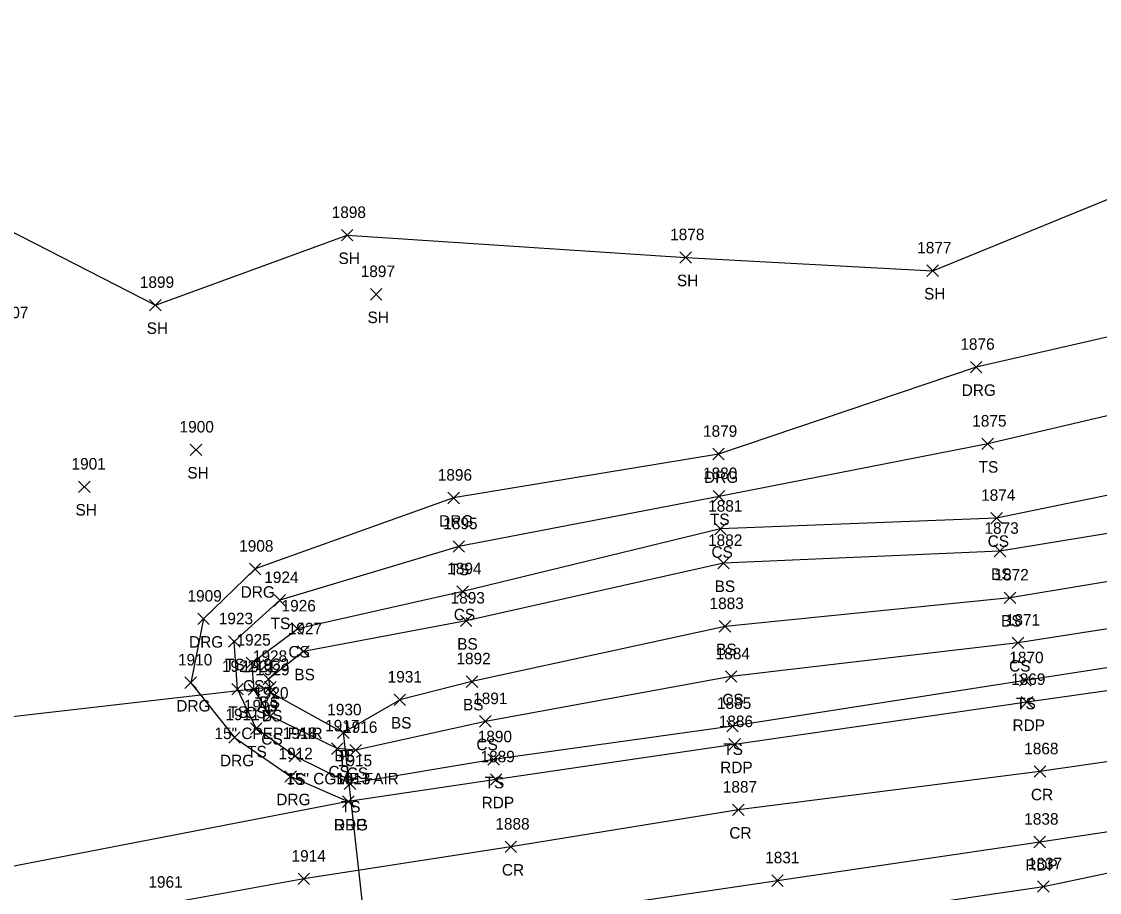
# Model space of a CAD drawing. Extents: x 1472233 to 1475777, y 540726 to 543442.
# Drawn here: x 1475192.5 to 1475379.6, y 543285.3 to 543436.6 of the extents above; entities that cross this region are included whole.
import ezdxf

# ---------------------------------------------------------------- set-up
doc = ezdxf.new("R2010")
doc.units = 0
for name, color, linetype in [('D_A', 7, 'Continuous'), ('D_C', 7, 'Continuous'), ('D_I', 7, 'Continuous'), ('D_TIC', 7, 'Continuous'), ('DCP', 7, 'Continuous'), ('L_A', 7, 'Continuous'), ('L_I', 7, 'Continuous'), ('L_TIC', 7, 'Continuous'), ('LELB', 7, 'Continuous'), ('LSOGP', 7, 'Continuous'), ('P_A', 7, 'Continuous'), ('P_I', 7, 'Continuous'), ('P_TIC', 7, 'Continuous'), ('PET', 7, 'Continuous'), ('PRC', 7, 'Continuous'), ('R_A', 7, 'Continuous'), ('R_I', 7, 'Continuous'), ('R_TIC', 7, 'Continuous'), ('RDG', 7, 'Continuous')]:
    doc.layers.add(name, color=color, linetype=linetype)

msp = doc.modelspace()

# ---------------------------------------------------------------- linework, layer by layer
at = {"layer": 'D_TIC'}
for points in [[(1475234.68, 543319.97), (1475236.68, 543321.97)], [(1475236.68, 543319.97), (1475234.68, 543321.97)], [(1475247.33, 543312.1), (1475249.33, 543314.1)], [(1475249.33, 543312.1), (1475247.33, 543314.1)]]:
    msp.add_lwpolyline(points, dxfattribs=at)
at = {"layer": 'DCP'}
for points in [[(1475235.68, 543320.97), (1475182.74, 543314.89)], [(1475248.33, 543313.1), (1475253.84, 543263.18)]]:
    msp.add_lwpolyline(points, dxfattribs=at)
at = {"layer": 'L_TIC'}
for points in [[(1475248.02, 543398.5), (1475250.02, 543400.5)], [(1475250.02, 543398.5), (1475248.02, 543400.5)], [(1475306.77, 543394.64), (1475308.77, 543396.64)], [(1475308.77, 543394.64), (1475306.77, 543396.64)], [(1475349.65, 543392.34), (1475351.65, 543394.34)], [(1475351.65, 543392.34), (1475349.65, 543394.34)], [(1475253.05, 543388.23), (1475255.05, 543390.23)], [(1475255.05, 543388.23), (1475253.05, 543390.23)], [(1475214.72, 543386.35), (1475216.72, 543388.35)], [(1475216.72, 543386.35), (1475214.72, 543388.35)], [(1475221.78, 543361.23), (1475223.78, 543363.23)], [(1475223.78, 543361.23), (1475221.78, 543363.23)], [(1475359.2, 543362.25), (1475361.2, 543364.25)], [(1475361.2, 543362.25), (1475359.2, 543364.25)], [(1475202.37, 543354.8), (1475204.37, 543356.8)], [(1475204.37, 543354.8), (1475202.37, 543356.8)], [(1475312.56, 543353.14), (1475314.56, 543355.14)], [(1475314.56, 543353.14), (1475312.56, 543355.14)], [(1475360.74, 543349.36), (1475362.74, 543351.36)], [(1475362.74, 543349.36), (1475360.74, 543351.36)], [(1475312.8, 543347.47), (1475314.8, 543349.47)], [(1475314.8, 543347.47), (1475312.8, 543349.47)], [(1475267.38, 543344.43), (1475269.38, 543346.43)], [(1475269.38, 543344.43), (1475267.38, 543346.43)], [(1475361.32, 543343.63), (1475363.32, 543345.63)], [(1475363.32, 543343.63), (1475361.32, 543345.63)], [(1475313.34, 543341.52), (1475315.34, 543343.52)], [(1475315.34, 543341.52), (1475313.34, 543343.52)], [(1475236.31, 543335.08), (1475238.31, 543337.08)], [(1475238.31, 543335.08), (1475236.31, 543337.08)], [(1475236.31, 543335.08), (1475238.31, 543337.08)], [(1475238.31, 543335.08), (1475236.31, 543337.08)], [(1475268.07, 543336.6), (1475270.07, 543338.6)], [(1475270.07, 543336.6), (1475268.07, 543338.6)], [(1475363.07, 543335.52), (1475365.07, 543337.52)], [(1475365.07, 543335.52), (1475363.07, 543337.52)], [(1475268.66, 543331.51), (1475270.66, 543333.51)], [(1475270.66, 543331.51), (1475268.66, 543333.51)], [(1475239.36, 543330.14), (1475241.36, 543332.14)], [(1475241.36, 543330.14), (1475239.36, 543332.14)], [(1475239.36, 543330.14), (1475241.36, 543332.14)], [(1475241.36, 543330.14), (1475239.36, 543332.14)], [(1475313.6, 543330.55), (1475315.6, 543332.55)], [(1475315.6, 543330.55), (1475313.6, 543332.55)], [(1475228.41, 543327.92), (1475230.41, 543329.92)], [(1475230.41, 543327.92), (1475228.41, 543329.92)], [(1475364.47, 543327.7), (1475366.47, 543329.7)], [(1475366.47, 543327.7), (1475364.47, 543329.7)], [(1475240.4, 543326.18), (1475242.4, 543328.18)], [(1475242.4, 543326.18), (1475240.4, 543328.18)], [(1475231.48, 543324.21), (1475233.48, 543326.21)], [(1475233.48, 543324.21), (1475231.48, 543326.21)], [(1475234.34, 543321.38), (1475236.34, 543323.38)], [(1475236.34, 543321.38), (1475234.34, 543323.38)], [(1475269.67, 543320.96), (1475271.67, 543322.96)], [(1475271.67, 543320.96), (1475269.67, 543322.96)], [(1475314.67, 543321.83), (1475316.67, 543323.83)], [(1475316.67, 543321.83), (1475314.67, 543323.83)], [(1475365.72, 543321.15), (1475367.72, 543323.15)], [(1475367.72, 543321.15), (1475365.72, 543323.15)], [(1475228.97, 543319.65), (1475230.97, 543321.65)], [(1475230.97, 543319.65), (1475228.97, 543321.65)], [(1475231.85, 543319.59), (1475233.85, 543321.59)], [(1475233.85, 543319.59), (1475231.85, 543321.59)], [(1475234.76, 543319.05), (1475236.76, 543321.05)], [(1475236.76, 543319.05), (1475234.76, 543321.05)], [(1475257.16, 543317.8), (1475259.16, 543319.8)], [(1475259.16, 543317.8), (1475257.16, 543319.8)], [(1475257.16, 543317.8), (1475259.16, 543319.8)], [(1475259.16, 543317.8), (1475257.16, 543319.8)], [(1475234.66, 543315), (1475236.66, 543317)], [(1475236.66, 543315), (1475234.66, 543317)], [(1475232.22, 543312.79), (1475234.22, 543314.79)], [(1475234.22, 543312.79), (1475232.22, 543314.79)], [(1475272, 543314.04), (1475274, 543316.04)], [(1475274, 543314.04), (1475272, 543316.04)], [(1475314.89, 543313.22), (1475316.89, 543315.22)], [(1475316.89, 543313.22), (1475314.89, 543315.22)], [(1475247.33, 543312.1), (1475249.33, 543314.1)], [(1475249.33, 543312.1), (1475247.33, 543314.1)], [(1475246.3, 543309.31), (1475248.3, 543311.31)], [(1475248.3, 543309.31), (1475246.3, 543311.31)], [(1475249.49, 543309.05), (1475251.49, 543311.05)], [(1475251.49, 543309.05), (1475249.49, 543311.05)], [(1475238.94, 543308), (1475240.94, 543310)], [(1475240.94, 543308), (1475238.94, 543310)], [(1475273.45, 543307.42), (1475275.45, 543309.42)], [(1475275.45, 543307.42), (1475273.45, 543309.42)], [(1475248.51, 543303.24), (1475250.51, 543305.24)], [(1475250.51, 543303.24), (1475248.51, 543305.24)], [(1475368.86, 543285.35), (1475370.86, 543287.35)], [(1475370.86, 543285.35), (1475368.86, 543287.35)]]:
    msp.add_lwpolyline(points, dxfattribs=at)
at = {"layer": 'LELB'}
for points in [[(1475453.86, 543383.84), (1475412.78, 543375.62), (1475360.2, 543363.25), (1475313.56, 543354.14), (1475268.38, 543345.43), (1475237.31, 543336.08)], [(1475458.45, 543363.65), (1475414.07, 543361.09), (1475361.74, 543350.36), (1475313.8, 543348.47), (1475269.07, 543337.6), (1475240.36, 543331.14)], [(1475459.28, 543356.57), (1475414.21, 543353.1), (1475362.32, 543344.63), (1475314.34, 543342.52), (1475269.66, 543332.51), (1475241.4, 543327.18), (1475235.34, 543322.38), (1475235.76, 543320.05), (1475248.33, 543313.1), (1475258.16, 543318.8)], [(1475459.86, 543350.78), (1475417.09, 543345.32), (1475364.07, 543336.52), (1475314.6, 543331.55), (1475270.67, 543321.96), (1475258.16, 543318.8)], [(1475460.84, 543342.99), (1475416.96, 543336.74), (1475365.47, 543328.7), (1475315.67, 543322.83), (1475273, 543315.04), (1475250.49, 543310.05), (1475247.3, 543310.31), (1475235.66, 543316), (1475232.85, 543320.59), (1475232.48, 543325.21), (1475240.36, 543331.14)], [(1475461.98, 543336.03), (1475417.45, 543330.03), (1475366.72, 543322.15), (1475315.89, 543314.22), (1475274.45, 543308.42), (1475249.51, 543304.24), (1475239.94, 543309), (1475233.22, 543313.79), (1475229.97, 543320.65), (1475229.41, 543328.92), (1475237.31, 543336.08)], [(1475154.58, 543252.15), (1475203.22, 543262.61), (1475246.6, 543268.28), (1475255.93, 543270.01), (1475266.88, 543271.35), (1475278.04, 543272.27), (1475324.55, 543279.73), (1475369.86, 543286.35), (1475414.45, 543295.77), (1475466.95, 543301.49)]]:
    msp.add_lwpolyline(points, dxfattribs=at)
at = {"layer": 'LSOGP'}
msp.add_lwpolyline([(1475175.93, 543407.71), (1475215.72, 543387.35), (1475249.02, 543399.5), (1475307.77, 543395.64), (1475350.65, 543393.34), (1475414.2, 543419.32)], dxfattribs=at)
at = {"layer": 'P_TIC'}
for points in [[(1475366.01, 543317.38), (1475368.01, 543319.38)], [(1475368.01, 543317.38), (1475366.01, 543319.38)], [(1475315.26, 543310.05), (1475317.26, 543312.05)], [(1475317.26, 543310.05), (1475315.26, 543312.05)], [(1475368.27, 543305.33), (1475370.27, 543307.33)], [(1475370.27, 543305.33), (1475368.27, 543307.33)], [(1475273.86, 543303.94), (1475275.86, 543305.94)], [(1475275.86, 543303.94), (1475273.86, 543305.94)], [(1475248.21, 543300.1), (1475250.21, 543302.1)], [(1475250.21, 543300.1), (1475248.21, 543302.1)], [(1475315.91, 543298.68), (1475317.91, 543300.68)], [(1475317.91, 543298.68), (1475315.91, 543300.68)], [(1475276.43, 543292.25), (1475278.43, 543294.25)], [(1475278.43, 543292.25), (1475276.43, 543294.25)], [(1475368.23, 543293.1), (1475370.23, 543295.1)], [(1475370.23, 543293.1), (1475368.23, 543295.1)], [(1475240.48, 543286.69), (1475242.48, 543288.69)], [(1475242.48, 543286.69), (1475240.48, 543288.69)], [(1475322.7, 543286.39), (1475324.7, 543288.39)], [(1475324.7, 543286.39), (1475322.7, 543288.39)]]:
    msp.add_lwpolyline(points, dxfattribs=at)
at = {"layer": 'PET'}
for points in [[(1475462.95, 543331.81), (1475417.84, 543325.59), (1475367.01, 543318.38), (1475316.26, 543311.05), (1475274.86, 543304.94), (1475249.21, 543301.1), (1475175.88, 543286.93), (1475120.06, 543270.79), (1475090.24, 543260.11)], [(1475087.91, 543220.85), (1475087.19, 543228.55), (1475096.96, 543238.31), (1475120.81, 543245.65), (1475153.05, 543255.59), (1475202.33, 543267.68), (1475249.58, 543276.45), (1475275.49, 543280.28), (1475323.7, 543287.39), (1475369.23, 543294.1), (1475413.44, 543300.77), (1475466.08, 543307.86)]]:
    msp.add_lwpolyline(points, dxfattribs=at)
at = {"layer": 'PRC'}
msp.add_lwpolyline([(1475464.44, 543319.89), (1475419.21, 543313.59), (1475369.27, 543306.33), (1475316.91, 543299.68), (1475277.43, 543293.25), (1475241.48, 543287.69), (1475216.67, 543283.15), (1475196.71, 543279.7), (1475164.53, 543271.59), (1475122.11, 543258.81), (1475079.2, 543242.94)], dxfattribs=at)
at = {"layer": 'R_TIC'}
for points in [[(1475357.2, 543375.59), (1475359.2, 543377.59)], [(1475359.2, 543375.59), (1475357.2, 543377.59)], [(1475312.47, 543360.48), (1475314.47, 543362.48)], [(1475314.47, 543360.48), (1475312.47, 543362.48)], [(1475266.48, 543352.86), (1475268.48, 543354.86)], [(1475268.48, 543352.86), (1475266.48, 543354.86)], [(1475232.03, 543340.53), (1475234.03, 543342.53)], [(1475234.03, 543340.53), (1475232.03, 543342.53)], [(1475223.07, 543331.85), (1475225.07, 543333.85)], [(1475225.07, 543331.85), (1475223.07, 543333.85)], [(1475220.85, 543320.76), (1475222.85, 543322.76)], [(1475222.85, 543320.76), (1475220.85, 543322.76)], [(1475228.44, 543311.25), (1475230.44, 543313.25)], [(1475230.44, 543311.25), (1475228.44, 543313.25)], [(1475238.21, 543304.48), (1475240.21, 543306.48)], [(1475240.21, 543304.48), (1475238.21, 543306.48)], [(1475248.21, 543300.1), (1475250.21, 543302.1)], [(1475250.21, 543300.1), (1475248.21, 543302.1)]]:
    msp.add_lwpolyline(points, dxfattribs=at)
at = {"layer": 'RDG'}
msp.add_lwpolyline([(1475446.95, 543436.62), (1475452.5, 543394.75), (1475410.98, 543388.67), (1475358.2, 543376.59), (1475313.47, 543361.48), (1475267.48, 543353.86), (1475233.03, 543341.53), (1475224.07, 543332.85), (1475221.85, 543321.76), (1475229.44, 543312.25), (1475239.21, 543305.48), (1475249.21, 543301.1)], dxfattribs=at)

# ---------------------------------------------------------------- texts
at = {"layer": 'D_A'}
for p in [(1475235.06, 543315.97), (1475247.71, 543308.1)]:
    msp.add_text('P', height=2, dxfattribs=at).set_placement(p)
at = {"layer": 'D_C'}
for s, p in [('15" CPEP FAIR', (1475225.97, 543311.97)), ('15" CGMP FAIR', (1475238.45, 543304.1))]:
    msp.add_text(s, height=2, dxfattribs=at).set_placement(p)
at = {"layer": 'D_I'}
for s, p in [('1933', (1475232.99, 543323.97)), ('1930', (1475245.55, 543316.1))]:
    msp.add_text(s, height=2, dxfattribs=at).set_placement(p)
at = {"layer": 'L_A'}
for s, p in [('SH', (1475247.5, 543394.5)), ('SH', (1475306.25, 543390.64)), ('SH', (1475349.14, 543388.34)), ('SH', (1475252.54, 543384.23)), ('SH', (1475214.2, 543382.35)), ('TS', (1475358.61, 543358.25)), ('SH', (1475221.26, 543357.23)), ('SH', (1475201.85, 543350.8)), ('TS', (1475311.97, 543349.14)), ('CS', (1475360.19, 543345.36)), ('CS', (1475312.24, 543343.47)), ('TS', (1475266.79, 543340.43)), ('BS', (1475360.76, 543339.63)), ('BS', (1475312.79, 543337.52)), ('CS', (1475267.51, 543332.6)), ('BS', (1475362.51, 543331.52)), ('TS', (1475235.72, 543331.08)), ('TS', (1475235.72, 543331.08)), ('BS', (1475268.1, 543327.51)), ('CS', (1475238.81, 543326.14)), ('CS', (1475238.81, 543326.14)), ('BS', (1475313.05, 543326.55)), ('TS', (1475227.82, 543323.92)), ('CS', (1475363.91, 543323.7)), ('BS', (1475239.84, 543322.18)), ('CS', (1475230.92, 543320.21)), ('BS', (1475233.78, 543317.38)), ('BS', (1475269.11, 543316.96)), ('CS', (1475314.11, 543317.83)), ('TS', (1475365.13, 543317.15)), ('TS', (1475228.38, 543315.65)), ('CS', (1475231.29, 543315.59)), ('BS', (1475234.2, 543315.05)), ('BS', (1475256.6, 543313.8)), ('BS', (1475256.6, 543313.8)), ('CS', (1475234.1, 543311)), ('TS', (1475231.63, 543308.79)), ('CS', (1475271.44, 543310.04)), ('TS', (1475314.3, 543309.22)), ('BS', (1475246.77, 543308.1)), ('CS', (1475245.75, 543305.31)), ('CS', (1475248.93, 543305.05)), ('TS', (1475238.35, 543304)), ('TS', (1475272.86, 543303.42)), ('TS', (1475247.92, 543299.24))]:
    msp.add_text(s, height=2, dxfattribs=at).set_placement(p)
at = {"layer": 'L_I'}
for s, p in [('1898', (1475246.32, 543402.5)), ('1878', (1475305.07, 543398.64)), ('1877', (1475347.96, 543396.34)), ('1897', (1475251.36, 543392.23)), ('1899', (1475213.02, 543390.35)), ('1907', (1475187.73, 543385.08)), ('1900', (1475219.92, 543365.23)), ('1875', (1475357.51, 543366.25)), ('1901', (1475201.16, 543358.8)), ('1880', (1475310.78, 543357.14)), ('1874', (1475359.05, 543353.36)), ('1881', (1475311.67, 543351.47)), ('1895', (1475265.69, 543348.43)), ('1873', (1475359.63, 543347.63)), ('1882', (1475311.65, 543345.52)), ('1894', (1475266.38, 543340.6)), ('1924', (1475234.62, 543339.08)), ('1924', (1475234.62, 543339.08)), ('1872', (1475361.38, 543339.52)), ('1893', (1475266.96, 543335.51)), ('1926', (1475237.62, 543334.14)), ('1926', (1475237.62, 543334.14)), ('1883', (1475311.91, 543334.55)), ('1923', (1475226.72, 543331.92)), ('1871', (1475363.35, 543331.7)), ('1927', (1475238.7, 543330.18)), ('1925', (1475229.79, 543328.21)), ('1884', (1475312.97, 543325.83)), ('1928', (1475232.64, 543325.38)), ('1892', (1475267.97, 543324.96)), ('1870', (1475363.94, 543325.15)), ('1922', (1475227.28, 543323.65)), ('1921', (1475230.73, 543323.59)), ('1929', (1475233.06, 543323.05)), ('1931', (1475256.03, 543321.8)), ('1931', (1475256.03, 543321.8)), ('1920', (1475232.88, 543319)), ('1919', (1475231.08, 543316.79)), ('1891', (1475270.88, 543318.04)), ('1885', (1475313.2, 543317.22)), ('1930', (1475245.55, 543316.1)), ('1917', (1475245.18, 543313.31)), ('1916', (1475248.3, 543313.05)), ('1918', (1475237.81, 543312)), ('1890', (1475271.67, 543311.42)), ('1915', (1475247.39, 543307.24)), ('1837', (1475367.17, 543289.35))]:
    msp.add_text(s, height=2, dxfattribs=at).set_placement(p)
at = {"layer": 'P_A'}
for s, p in [('RDP', (1475364.5, 543313.38)), ('RDP', (1475313.75, 543306.05)), ('CR', (1475367.7, 543301.33)), ('RDP', (1475272.35, 543299.94)), ('RDP', (1475246.69, 543296.1)), ('CR', (1475315.34, 543294.68)), ('CR', (1475275.86, 543288.25)), ('RDP', (1475366.72, 543289.1))]:
    msp.add_text(s, height=2, dxfattribs=at).set_placement(p)
at = {"layer": 'P_I'}
for s, p in [('1869', (1475364.26, 543321.38)), ('1886', (1475313.51, 543314.05)), ('1868', (1475366.53, 543309.33)), ('1889', (1475272.16, 543307.94)), ('1913', (1475247.08, 543304.1)), ('1887', (1475314.21, 543302.68)), ('1888', (1475274.73, 543296.25)), ('1838', (1475366.54, 543297.1)), ('1914', (1475239.35, 543290.69)), ('1831', (1475321.57, 543290.39)), ('1961', (1475214.5, 543286.15))]:
    msp.add_text(s, height=2, dxfattribs=at).set_placement(p)
at = {"layer": 'R_A'}
for p in [(1475355.68, 543371.59), (1475310.96, 543356.48), (1475264.97, 543348.86), (1475230.52, 543336.53), (1475221.56, 543327.85), (1475219.34, 543316.76), (1475226.93, 543307.25), (1475236.7, 543300.48), (1475246.69, 543296.1)]:
    msp.add_text('DRG', height=2, dxfattribs=at).set_placement(p)
at = {"layer": 'R_I'}
for s, p in [('1876', (1475355.45, 543379.59)), ('1879', (1475310.77, 543364.48)), ('1896', (1475264.73, 543356.86)), ('1908', (1475230.26, 543344.53)), ('1909', (1475221.29, 543335.85)), ('1910', (1475219.64, 543324.76)), ('1911', (1475227.88, 543315.25)), ('1912', (1475237.09, 543308.48)), ('1913', (1475247.08, 543304.1))]:
    msp.add_text(s, height=2, dxfattribs=at).set_placement(p)

doc.saveas('drawing.dxf')
